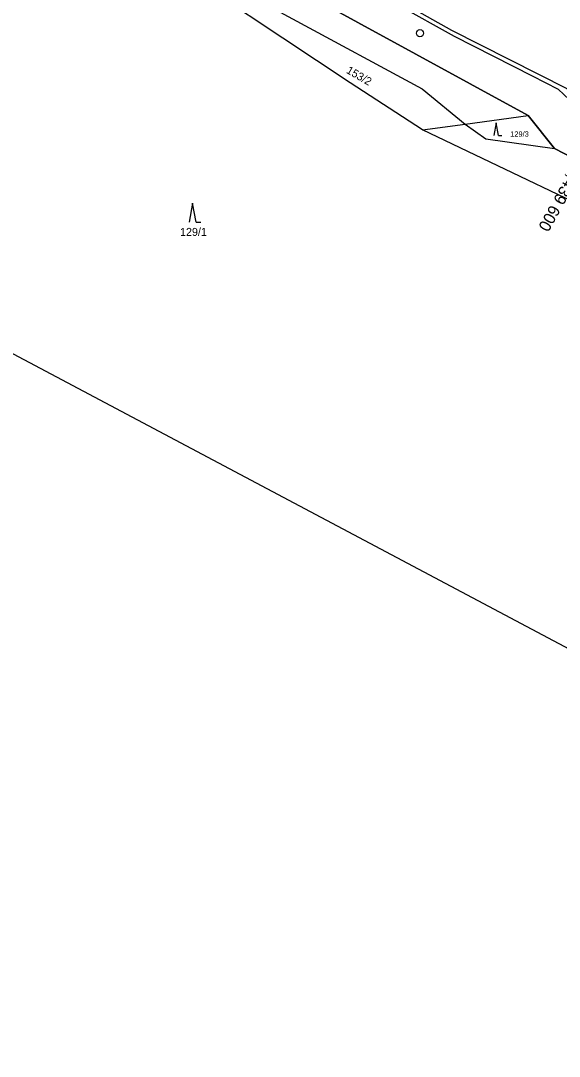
# Model space of a CAD drawing. Extents: x -793666 to -785424, y -1118958 to -1108761.
# Drawn here: x -789837.9 to -789723.6, y -1114443.5 to -1114223.4 of the extents above; entities that cross this region are included whole.
import ezdxf

# ---------------------------------------------------------------- set-up
doc = ezdxf.new("R2010")
doc.units = 0
for name, color, linetype in [('1', 7, 'Continuous'), ('1_2000 - úřady', 7, 'Continuous'), ('Hranice parcel', 7, 'Continuous'), ('Parcelní čísla', 7, 'Continuous'), ('Vrstva 53', 7, 'Continuous'), ('Značky kultur', 7, 'Continuous')]:
    doc.layers.add(name, color=color, linetype=linetype)

msp = doc.modelspace()

# ---------------------------------------------------------------- linework, layer by layer
at = {"layer": '1'}
for points in [[(-790097.65, -1114005.61), (-790092.51, -1114013.51), (-790087.58, -1114018.78), (-790081.27, -1114023.48), (-790070.39, -1114034.8), (-790059.64, -1114044.51), (-790044.53, -1114057.48), (-790029.1, -1114068.39), (-790020.34, -1114073.4), (-790011.12, -1114079.5), (-789997.53, -1114087.43), (-789990.59, -1114091.36), (-789990, -1114090.71), (-789957.24, -1114108), (-789914.92, -1114130.33), (-789897.47, -1114140.42), (-789868.89, -1114156.49), (-789842.11, -1114173.75), (-789808.41, -1114192.36), (-789781.82, -1114206.71), (-789745.94, -1114226.72), (-789729.37, -1114235.18)], [(-789729.37, -1114235.18), (-789723.86, -1114238), (-789721.43, -1114240.25), (-789715.58, -1114243.5), (-789712.53, -1114244.57), (-789693.8, -1114256.22), (-789674.69, -1114266.08), (-789667.23, -1114269.28), (-789659.83, -1114272.47), (-789642.29, -1114278.58), (-789637.66, -1114279.92), (-789636.67, -1114276.5), (-789634.93, -1114276.11), (-789616.44, -1114277), (-789610.6, -1114282.06), (-789604.23, -1114283.25)], [(-789729.37, -1114235.18), (-789723.86, -1114238), (-789721.43, -1114240.25), (-789715.58, -1114243.5), (-789712.53, -1114244.57), (-789693.8, -1114256.22), (-789674.69, -1114266.08), (-789667.23, -1114269.28), (-789659.83, -1114272.47), (-789642.29, -1114278.58), (-789637.66, -1114279.92), (-789636.67, -1114276.5), (-789634.93, -1114276.11), (-789616.44, -1114277), (-789610.6, -1114282.06), (-789604.23, -1114283.25)]]:
    msp.add_lwpolyline(points, dxfattribs=at)
msp.add_circle((-789753.18, -1114226.09), 0.75, dxfattribs=at)
at = {"layer": '1_2000 - úřady'}
msp.add_lwpolyline([(-790360.41, -1114017.5), (-789388.79, -1114533.68), (-789259.98, -1114291.21)], dxfattribs=at)
at = {"layer": 'Hranice parcel'}
for p, q in [((-789743.58, -1114245.39), (-789730.23, -1114243.59)), ((-789730.23, -1114243.59), (-789724.61, -1114250.58)), ((-789752.62, -1114246.61), (-789743.58, -1114245.39))]:
    msp.add_line(p, q, dxfattribs=at)
for points in [[(-789891.43, -1114142.08), (-789830.15, -1114178.38), (-789746.5, -1114225.43), (-789721.98, -1114237.82)], [(-789891.39, -1114158.73), (-789844.34, -1114181.96), (-789790.24, -1114210.69), (-789730.23, -1114243.59)], [(-789832.77, -1114192.7), (-789807.81, -1114208.12), (-789752.68, -1114237.93), (-789743.58, -1114245.39)], [(-789752.62, -1114246.61), (-789768.02, -1114236.62), (-789811.09, -1114207.93), (-789832.77, -1114192.7)], [(-789672.8, -1114282.32), (-789703.15, -1114270.28), (-789752.62, -1114246.61)], [(-789743.58, -1114245.39), (-789739.19, -1114248.51), (-789724.61, -1114250.58)], [(-789724.61, -1114250.58), (-789675.34, -1114276.11), (-789672.68, -1114277.31)]]:
    msp.add_lwpolyline(points, dxfattribs=at)
at = {"layer": 'Vrstva 53'}
for points in [[(-790049.23, -1114034.44), (-790014.82, -1114057.41), (-790011.64, -1114059.53), (-790007.66, -1114062.18), (-790004.95, -1114067.14), (-789993.35, -1114088.34), (-789984.83, -1114079.42), (-789951.34, -1114096.74), (-789913.42, -1114129.06), (-789891.43, -1114142.08), (-789830.15, -1114178.38), (-789746.5, -1114225.43), (-789721.98, -1114237.82), (-789717.72, -1114240.35), (-789691.28, -1114256.01), (-789665.23, -1114268.84), (-789640.19, -1114272.7), (-789627.07, -1114282.33), (-789607.19, -1114286.63), (-789603.91, -1114286.39)], [(-789600.46, -1114294.39), (-789619.3, -1114290.36), (-789624.34, -1114291.37), (-789641.23, -1114287.32), (-789672.68, -1114277.31), (-789675.34, -1114276.11), (-789724.61, -1114250.58), (-789730.23, -1114243.59), (-789790.24, -1114210.69), (-789844.34, -1114181.96), (-789891.39, -1114158.73), (-789943.99, -1114130.82), (-789972.38, -1114117.19), (-789989.47, -1114115.38), (-790009.42, -1114105.25), (-790039.99, -1114089.61), (-790043.48, -1114088.64), (-790052.2, -1114080.82), (-790070.36, -1114064.18)]]:
    msp.add_lwpolyline(points, dxfattribs=at)
at = {"layer": 'Značky kultur'}
for p, q in [((-789736.99, -1114245.17), (-789737.49, -1114247.85)), ((-789736.49, -1114247.85), (-789736.99, -1114245.17)), ((-789736.49, -1114247.85), (-789735.82, -1114247.85)), ((-789801.46, -1114262.22), (-789802.21, -1114266.22)), ((-789800.71, -1114266.22), (-789801.46, -1114262.22)), ((-789800.71, -1114266.22), (-789799.71, -1114266.22))]:
    msp.add_line(p, q, dxfattribs=at)

# ---------------------------------------------------------------- texts
at = {"layer": '1'}
msp.add_text('km 28,439 600', height=2.5, rotation=240.9213, dxfattribs=at).set_placement((-789717.39, -1114247.96))
at = {"layer": 'Parcelní čísla'}
msp.add_text('153/2', height=1.7, rotation=330, dxfattribs=at).set_placement((-789768.98, -1114234.45))
for s, height, p in [('129/3', 1.14, (-789734.02, -1114248.09)), ('129/1', 1.7, (-789804.12, -1114269.17))]:
    msp.add_text(s, height=height, dxfattribs=at).set_placement(p)

doc.saveas('drawing.dxf')
